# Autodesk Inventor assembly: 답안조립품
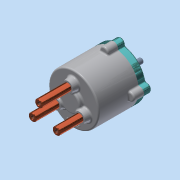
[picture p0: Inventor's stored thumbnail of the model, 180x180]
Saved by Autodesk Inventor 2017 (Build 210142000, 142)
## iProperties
Part Number: 답안조립품
Material: 일반
Document SubType Name: Assembly
Designer: MRC
Mass: 1236.63 g
Surface Area: 1770.13 cm^2
Volume: 433.788 cm^3
Density: 2.85078 g/cm^3
Author: MRC
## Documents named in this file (14)
- C:\Users\MRC\Desktop\610708V1002 (1)\답안조립품.iam
- C:\Users\MRC\Desktop\610708V1002 (1)\본체.ipt
- C:\Users\MRC\Desktop\610708V1002 (1)\가변스프링1.ipt
- C:\Users\MRC\Desktop\610708V1002 (1)\가변스프링2.ipt
- C:\Users\MRC\Desktop\610708V1002 (1)\가변스프링3.ipt
- C:\Users\MRC\Desktop\610708V1002 (1)\멈춤링 10 x 1.ipt
- C:\Users\MRC\Desktop\610708V1002 (1)\멈춤링 22 x 1.2.ipt
- C:\Users\MRC\Desktop\610708V1002 (1)\메인 축.ipt
- C:\Users\MRC\Desktop\610708V1002 (1)\베어링 NA 4900.ipt
- C:\Users\MRC\Desktop\610708V1002 (1)\볼트 M5.ipt
- C:\Users\MRC\Desktop\610708V1002 (1)\슬라이드 축.ipt
- C:\Users\MRC\Desktop\610708V1002 (1)\오일실.ipt
- C:\Users\MRC\Desktop\610708V1002 (1)\커버.ipt
- C:\Users\MRC\Desktop\610708V1002 (1)\판캠.ipt
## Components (3 placed, 3 different names)
1. 가변스프링1:1
2. 가변스프링2:1
3. 가변스프링3:1
